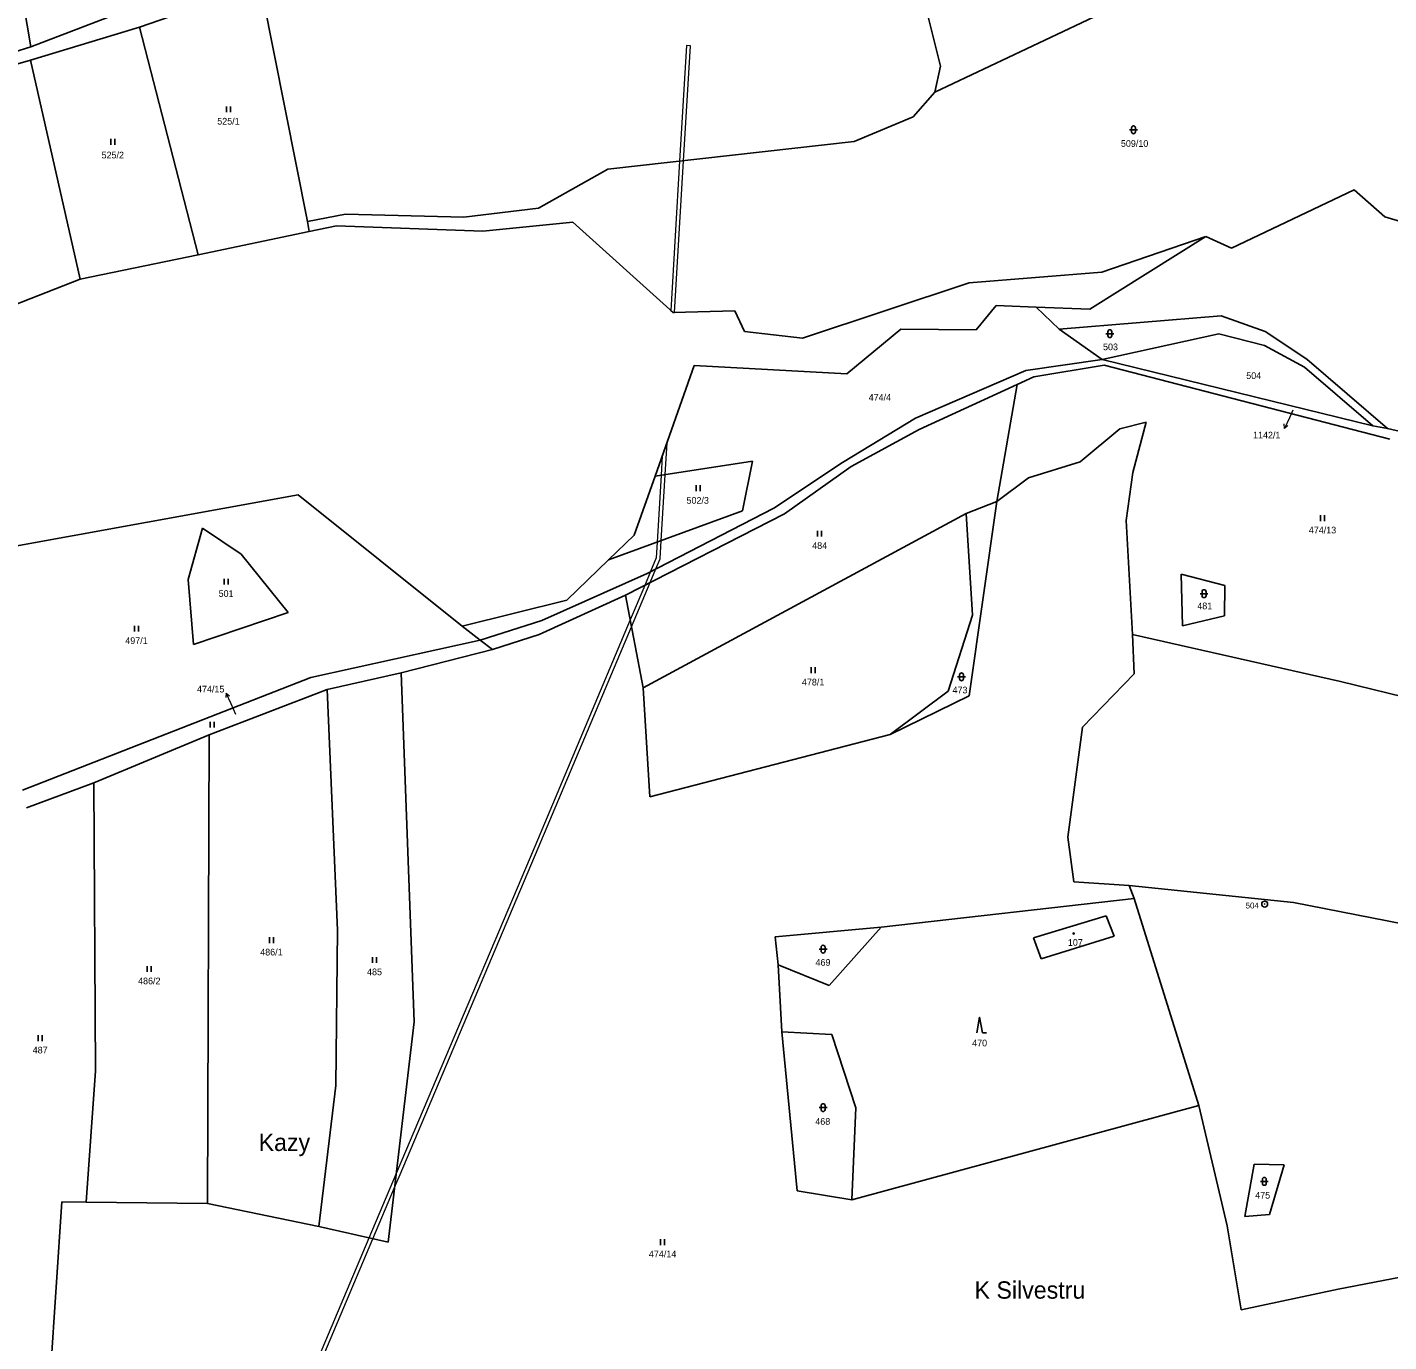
# Model space of a CAD drawing. Extents: x -765428 to -762163, y -1107632 to -1104975.
# Drawn here: x -764695.4 to -764349.6, y -1106368.4 to -1106034.3 of the extents above; entities that cross this region are included whole.
import ezdxf
from ezdxf.enums import TextEntityAlignment as Align

# ---------------------------------------------------------------- set-up
doc = ezdxf.new("R2010")
doc.units = 0
doc.header["$LTSCALE"] = 0.68
for name, color, linetype, lineweight in [('1', 7, 'Continuous', 25), ('13', 7, 'Continuous', 13), ('3', 7, 'Continuous', 25), ('5', 7, 'Continuous', 25), ('7', 7, 'Continuous', 13), ('8', 7, 'Continuous', 25)]:
    doc.layers.add(name, color=color, linetype=linetype, lineweight=lineweight)
doc.layers.add('2', color=7, linetype='Continuous')

msp = doc.modelspace()

# ---------------------------------------------------------------- linework, layer by layer
at = {"layer": '1'}
for p, q in [((-764479.66, -1105978.64), (-764463.45, -1106044.21)), ((-764659.81, -1106025.95), (-764694.55, -1106039.31)), ((-764636.2, -1106023.64), (-764666.9, -1106034.32)), ((-764624.21, -1106083.66), (-764636.2, -1106023.64)), ((-764411.29, -1106025.42), (-764464.92, -1106050.85)), ((-764666.9, -1106034.32), (-764694.57, -1106042.64)), ((-764666.9, -1106034.32), (-764652.02, -1106092.11)), ((-764694.55, -1106039.31), (-764729.59, -1106050.22)), ((-764694.57, -1106042.64), (-764729.45, -1106052.83)), ((-764681.98, -1106098.33), (-764694.57, -1106042.64)), ((-764463.45, -1106044.21), (-764464.92, -1106050.85)), ((-764464.92, -1106050.85), (-764470.36, -1106057.08)), ((-764470.36, -1106057.08), (-764485.37, -1106063.35)), ((-764485.37, -1106063.35), (-764547.95, -1106070.38)), ((-764547.95, -1106070.38), (-764565.59, -1106080.25)), ((-764358.34, -1106075.59), (-764389.51, -1106090.49)), ((-764350.58, -1106082.49), (-764358.34, -1106075.59)), ((-764614.6, -1106081.83), (-764624.21, -1106083.66)), ((-764584.5, -1106082.56), (-764614.6, -1106081.83)), ((-764565.59, -1106080.25), (-764584.5, -1106082.56)), ((-764624.21, -1106083.66), (-764623.79, -1106086.24)), ((-764623.79, -1106086.24), (-764616.88, -1106084.8)), ((-764616.88, -1106084.8), (-764579.71, -1106086.14)), ((-764579.71, -1106086.14), (-764556.8, -1106083.81)), ((-764556.8, -1106083.81), (-764531.32, -1106106.82)), ((-764332.67, -1106087.84), (-764350.58, -1106082.49)), ((-764652.02, -1106092.11), (-764623.79, -1106086.24)), ((-764396.06, -1106087.47), (-764425.53, -1106106)), ((-764422.48, -1106096.59), (-764396.06, -1106087.47)), ((-764396.06, -1106087.47), (-764389.51, -1106090.49)), ((-764681.98, -1106098.33), (-764652.02, -1106092.11)), ((-764718.88, -1106112.84), (-764681.98, -1106098.33)), ((-764456.18, -1106099.28), (-764422.48, -1106096.59)), ((-764498.48, -1106113.34), (-764456.18, -1106099.28)), ((-764449.31, -1106105.07), (-764454.37, -1106111.19)), ((-764439.17, -1106105.47), (-764449.31, -1106105.07)), ((-764425.53, -1106106), (-764439.17, -1106105.47)), ((-764433.28, -1106111.06), (-764439.17, -1106105.47)), ((-764531.32, -1106106.82), (-764515.69, -1106106.39)), ((-764515.69, -1106106.39), (-764513.19, -1106111.61)), ((-764433.28, -1106111.06), (-764392.12, -1106107.67)), ((-764392.12, -1106107.67), (-764380.95, -1106111.67)), ((-764513.19, -1106111.61), (-764498.48, -1106113.34)), ((-764473.5, -1106111.06), (-764487.22, -1106122.36)), ((-764454.37, -1106111.19), (-764473.5, -1106111.06)), ((-764433.28, -1106111.06), (-764422.39, -1106118.73)), ((-764422.39, -1106118.73), (-764392.72, -1106112.26)), ((-764392.72, -1106112.26), (-764381.17, -1106115.18)), ((-764380.95, -1106111.67), (-764370.39, -1106118.67)), ((-764381.17, -1106115.18), (-764370.95, -1106120.72)), ((-764422.39, -1106118.73), (-764441.8, -1106121.53)), ((-764353.63, -1106135.63), (-764422.39, -1106118.73)), ((-764370.39, -1106118.67), (-764349.87, -1106136.31)), ((-764535.95, -1106148.42), (-764525.98, -1106120.24)), ((-764487.22, -1106122.36), (-764525.98, -1106120.24)), ((-764441.8, -1106121.53), (-764469.76, -1106133.68)), ((-764439.74, -1106123.2), (-764443.95, -1106125.13)), ((-764421.87, -1106120.22), (-764439.74, -1106123.2)), ((-764349.26, -1106138.97), (-764421.87, -1106120.22)), ((-764370.95, -1106120.72), (-764353.63, -1106135.63)), ((-764443.95, -1106125.13), (-764468.83, -1106136.58)), ((-764449.12, -1106154.87), (-764443.95, -1106125.13)), ((-764469.76, -1106133.68), (-764488.31, -1106144.9)), ((-764468.83, -1106136.58), (-764486.09, -1106145.98)), ((-764417.89, -1106136.38), (-764427.98, -1106144.79)), ((-764411.16, -1106134.68), (-764417.89, -1106136.38)), ((-764414.59, -1106147.49), (-764411.16, -1106134.68)), ((-764349.87, -1106136.31), (-764353.63, -1106135.63)), ((-764322.27, -1106142.59), (-764349.87, -1106136.31)), ((-764511.22, -1106144.61), (-764535.95, -1106148.42)), ((-764511.22, -1106144.61), (-764513.71, -1106157.24)), ((-764488.31, -1106144.9), (-764505.79, -1106156.56)), ((-764486.09, -1106145.98), (-764503.06, -1106157.95)), ((-764427.98, -1106144.79), (-764441.05, -1106148.82)), ((-764416.27, -1106159.67), (-764414.59, -1106147.49)), ((-764541.27, -1106163.43), (-764535.95, -1106148.42)), ((-764441.05, -1106148.82), (-764449.12, -1106154.87)), ((-764626.62, -1106153.16), (-764703.88, -1106167.16)), ((-764584.97, -1106186.56), (-764626.62, -1106153.16)), ((-764513.71, -1106157.24), (-764547.74, -1106169.67)), ((-764503.06, -1106157.95), (-764543.46, -1106178.68)), ((-764538.95, -1106202.23), (-764456.9, -1106157.88)), ((-764505.79, -1106156.56), (-764537.98, -1106173.12)), ((-764449.12, -1106154.87), (-764456.9, -1106157.88)), ((-764456.9, -1106157.88), (-764455.3, -1106183.73)), ((-764449.12, -1106154.87), (-764456.18, -1106204.24)), ((-764414.64, -1106188.67), (-764416.27, -1106159.67)), ((-764654.57, -1106174.7), (-764650.91, -1106161.58)), ((-764650.91, -1106161.58), (-764641.08, -1106168.27)), ((-764541.27, -1106163.43), (-764547.74, -1106169.67)), ((-764629.16, -1106183.09), (-764641.08, -1106168.27)), ((-764547.74, -1106169.67), (-764558.39, -1106179.96)), ((-764654.57, -1106174.7), (-764653.24, -1106191.16)), ((-764537.98, -1106173.12), (-764564.72, -1106185.08)), ((-764402.31, -1106173.32), (-764401.95, -1106186.44)), ((-764391.25, -1106176.18), (-764402.31, -1106173.32)), ((-764543.46, -1106178.68), (-764565.42, -1106188.68)), ((-764538.95, -1106202.23), (-764543.46, -1106178.68)), ((-764391.28, -1106183.92), (-764391.25, -1106176.18)), ((-764558.39, -1106179.96), (-764584.97, -1106186.56)), ((-764653.24, -1106191.16), (-764629.16, -1106183.09)), ((-764564.72, -1106185.08), (-764580.36, -1106190.07)), ((-764455.3, -1106183.73), (-764461.45, -1106203.04)), ((-764401.95, -1106186.44), (-764391.28, -1106183.92)), ((-764580.36, -1106190.07), (-764584.97, -1106186.56)), ((-764565.42, -1106188.68), (-764577.21, -1106192.49)), ((-764414.64, -1106188.67), (-764414.22, -1106198.62)), ((-764361.8, -1106200.63), (-764414.64, -1106188.67)), ((-764580.36, -1106190.07), (-764623.38, -1106199.56)), ((-764600.46, -1106198.36), (-764577.21, -1106192.49)), ((-764577.21, -1106192.49), (-764580.36, -1106190.07)), ((-764600.46, -1106198.36), (-764619.26, -1106202.61)), ((-764597.13, -1106287.13), (-764600.46, -1106198.36)), ((-764414.22, -1106198.62), (-764427.37, -1106212.24)), ((-764623.38, -1106199.56), (-764696.66, -1106228.18)), ((-764649.26, -1106214.16), (-764619.26, -1106202.61)), ((-764616.58, -1106263.81), (-764619.26, -1106202.61)), ((-764537.28, -1106229.92), (-764538.95, -1106202.23)), ((-764324.05, -1106209.8), (-764361.8, -1106200.63)), ((-764461.45, -1106203.04), (-764476.2, -1106214.05)), ((-764456.18, -1106204.24), (-764476.2, -1106214.05)), ((-764427.37, -1106212.24), (-764431.09, -1106240.18)), ((-764678.54, -1106226.38), (-764649.26, -1106214.16)), ((-764649.62, -1106333.24), (-764649.26, -1106214.16)), ((-764476.2, -1106214.05), (-764537.28, -1106229.92)), ((-764678.54, -1106226.38), (-764695.59, -1106232.66)), ((-764678.06, -1106299.53), (-764678.54, -1106226.38)), ((-764431.09, -1106240.18), (-764429.54, -1106251.48)), ((-764429.54, -1106251.48), (-764415.51, -1106252.4)), ((-764415.51, -1106252.4), (-764373.79, -1106256.8)), ((-764414.24, -1106255.78), (-764415.51, -1106252.4)), ((-764478.5, -1106263.01), (-764414.24, -1106255.78)), ((-764414.24, -1106255.78), (-764397.8, -1106308.36)), ((-764373.79, -1106256.8), (-764311.37, -1106269.03)), ((-764421.36, -1106260.16), (-764439.8, -1106265.76)), ((-764421.36, -1106260.16), (-764419.36, -1106265.3)), ((-764617.07, -1106303.26), (-764616.58, -1106263.81)), ((-764505.48, -1106265.49), (-764478.5, -1106263.01)), ((-764478.5, -1106263.01), (-764491.69, -1106277.89)), ((-764505.48, -1106265.49), (-764504.68, -1106272.6)), ((-764437.86, -1106271.12), (-764439.8, -1106265.76)), ((-764419.36, -1106265.3), (-764437.86, -1106271.12)), ((-764503.76, -1106289.67), (-764504.68, -1106272.6)), ((-764491.69, -1106277.89), (-764504.68, -1106272.6)), ((-764603.77, -1106343.13), (-764597.13, -1106287.13)), ((-764503.76, -1106289.67), (-764499.82, -1106330.05)), ((-764491.03, -1106290.32), (-764503.76, -1106289.67)), ((-764484.94, -1106308.96), (-764491.03, -1106290.32)), ((-764680.46, -1106332.91), (-764678.06, -1106299.53)), ((-764617.07, -1106303.26), (-764621.39, -1106339.15)), ((-764485.95, -1106332.32), (-764397.8, -1106308.36)), ((-764485.95, -1106332.32), (-764484.94, -1106308.96)), ((-764397.8, -1106308.36), (-764390.63, -1106338.98)), ((-764383.79, -1106323.26), (-764386.09, -1106336.57)), ((-764376.16, -1106323.42), (-764383.79, -1106323.26)), ((-764379.86, -1106336.06), (-764376.16, -1106323.42)), ((-764499.82, -1106330.05), (-764485.95, -1106332.32)), ((-764690.66, -1106394.2), (-764686.67, -1106332.83)), ((-764686.67, -1106332.83), (-764680.46, -1106332.91)), ((-764680.46, -1106332.91), (-764649.62, -1106333.24)), ((-764649.62, -1106333.24), (-764621.39, -1106339.15)), ((-764386.09, -1106336.57), (-764379.86, -1106336.06)), ((-764621.39, -1106339.15), (-764603.77, -1106343.13)), ((-764390.63, -1106338.98), (-764387.02, -1106360.28)), ((-764362.45, -1106355.01), (-764310.86, -1106345.11)), ((-764387.02, -1106360.28), (-764362.45, -1106355.01))]:
    msp.add_line(p, q, dxfattribs=at)
msp.add_lwpolyline([(-764713.46, -1105926.07), (-764700.09, -1106006.14), (-764694.55, -1106039.31)], dxfattribs=at)
at = {"layer": '13'}
for points in [[(-764530.97, -1106106.81), (-764528.69, -1106068.22), (-764526.97, -1106039.03), (-764527.97, -1106038.97), (-764529.7, -1106068.33), (-764531.94, -1106106.26), (-764531.32, -1106106.82)], [(-764534.41, -1106148.18), (-764533.39, -1106148.03), (-764532.91, -1106139.83), (-764534.11, -1106143.23)], [(-764535.41, -1106165.16), (-764534.38, -1106164.79), (-764533.39, -1106148.03), (-764534.41, -1106148.18)], [(-764537.1, -1106172.67), (-764535.72, -1106171.96), (-764534.66, -1106169.44), (-764534.38, -1106164.79), (-764535.41, -1106165.16), (-764535.64, -1106169.2)], [(-764538.58, -1106176.18), (-764537.2, -1106175.47), (-764535.72, -1106171.96), (-764537.1, -1106172.67)], [(-764542.26, -1106184.92), (-764541.93, -1106186.69), (-764537.2, -1106175.47), (-764538.58, -1106176.18)], [(-764653.41, -1106450.97), (-764640.59, -1106420.4), (-764634.82, -1106406.65), (-764607.62, -1106342.26), (-764602.12, -1106329.23), (-764600.71, -1106325.88), (-764565.61, -1106242.92), (-764541.93, -1106186.69), (-764542.26, -1106184.92), (-764566.53, -1106242.54), (-764601.7, -1106325.65), (-764608.62, -1106342.04), (-764635.74, -1106406.27), (-764641.65, -1106420.36), (-764654.47, -1106450.91)]]:
    msp.add_lwpolyline(points, close=True, dxfattribs=at)
at = {"layer": '3'}
for p, q in [((-764644.791, -1106055.92), (-764644.791, -1106054.42)), ((-764643.79, -1106055.92), (-764643.79, -1106054.42)), ((-764415.411, -1106060.361), (-764413.409, -1106060.361)), ((-764414.911, -1106059.861), (-764414.911, -1106060.862)), ((-764413.909, -1106060.862), (-764413.909, -1106059.861)), ((-764674.181, -1106064.16), (-764674.181, -1106062.66)), ((-764673.18, -1106064.16), (-764673.18, -1106062.66)), ((-764421.421, -1106112.191), (-764419.419, -1106112.191)), ((-764420.921, -1106111.691), (-764420.921, -1106112.692)), ((-764419.919, -1106112.692), (-764419.919, -1106111.691)), ((-764525.481, -1106152.23), (-764525.481, -1106150.73)), ((-764524.48, -1106152.23), (-764524.48, -1106150.73)), ((-764366.911, -1106159.83), (-764366.911, -1106158.33)), ((-764365.91, -1106159.83), (-764365.91, -1106158.33)), ((-764494.651, -1106163.78), (-764494.651, -1106162.28)), ((-764493.65, -1106163.78), (-764493.65, -1106162.28)), ((-764645.431, -1106175.97), (-764645.431, -1106174.47)), ((-764644.43, -1106175.97), (-764644.43, -1106174.47)), ((-764397.491, -1106178.271), (-764395.489, -1106178.271)), ((-764396.991, -1106177.771), (-764396.991, -1106178.772)), ((-764395.989, -1106178.772), (-764395.989, -1106177.771)), ((-764668.191, -1106187.92), (-764668.191, -1106186.42)), ((-764667.19, -1106187.92), (-764667.19, -1106186.42)), ((-764496.311, -1106198.47), (-764496.311, -1106196.97)), ((-764495.31, -1106198.47), (-764495.31, -1106196.97)), ((-764459.101, -1106199.411), (-764457.099, -1106199.411)), ((-764458.601, -1106198.911), (-764458.601, -1106199.912)), ((-764457.599, -1106199.912), (-764457.599, -1106198.911)), ((-764648.991, -1106212.31), (-764648.991, -1106210.81)), ((-764647.99, -1106212.31), (-764647.99, -1106210.81)), ((-764633.911, -1106267.09), (-764633.911, -1106265.59)), ((-764632.91, -1106267.09), (-764632.91, -1106265.59)), ((-764494.271, -1106268.631), (-764492.269, -1106268.631)), ((-764493.771, -1106268.131), (-764493.771, -1106269.132)), ((-764492.769, -1106269.132), (-764492.769, -1106268.131)), ((-764607.731, -1106272.12), (-764607.731, -1106270.62)), ((-764606.73, -1106272.12), (-764606.73, -1106270.62)), ((-764664.941, -1106274.42), (-764664.941, -1106272.92)), ((-764663.94, -1106274.42), (-764663.94, -1106272.92)), ((-764692.661, -1106292), (-764692.661, -1106290.5)), ((-764691.66, -1106292), (-764691.66, -1106290.5)), ((-764452.74, -1106289.92), (-764451.744, -1106289.92)), ((-764494.261, -1106308.891), (-764492.259, -1106308.891)), ((-764493.761, -1106308.391), (-764493.761, -1106309.392)), ((-764492.759, -1106309.392), (-764492.759, -1106308.391)), ((-764381.671, -1106327.141), (-764381.671, -1106328.142)), ((-764380.669, -1106328.142), (-764380.669, -1106327.141)), ((-764382.171, -1106327.641), (-764380.169, -1106327.641)), ((-764534.541, -1106343.83), (-764534.541, -1106342.33)), ((-764533.54, -1106343.83), (-764533.54, -1106342.33))]:
    msp.add_line(p, q, dxfattribs=at)
msp.add_lwpolyline([(-764452.74, -1106289.92), (-764453.49, -1106285.92), (-764454.24, -1106289.92)], dxfattribs=at)
for centre, start, end in [((-764414.41, -1106059.8609), 0, 180), ((-764414.41, -1106060.8609), 180, 359.98789), ((-764420.42, -1106111.6909), 0, 180), ((-764420.42, -1106112.6909), 180, 359.98789), ((-764396.49, -1106177.7709), 0, 180), ((-764396.49, -1106178.7709), 180, 359.98789), ((-764458.1, -1106198.9109), 0, 180), ((-764458.1, -1106199.9109), 180, 359.98789), ((-764493.27, -1106268.1309), 0, 180), ((-764493.27, -1106269.1309), 180, 359.98789), ((-764493.26, -1106308.3909), 0, 180), ((-764493.26, -1106309.3909), 180, 359.98789), ((-764381.17, -1106327.1409), 0, 180), ((-764381.17, -1106328.1409), 180, 359.98789)]:
    msp.add_arc(centre, 0.5, start, end, dxfattribs=at)
at = {"layer": '5'}
msp.add_circle((-764429.5968, -1106264.6392), 0.175, dxfattribs=at)
at = {"layer": '7'}
for p, q in [((-764376.088, -1106136.26), (-764375.211, -1106135.564)), ((-764644.918, -1106203.54), (-764644.949, -1106204.659))]:
    msp.add_line(p, q, dxfattribs=at)
for points in [[(-764373.94, -1106131.65), (-764374.82, -1106133.54), (-764376.088, -1106136.26), (-764376.119, -1106135.141)], [(-764642.41, -1106208.97), (-764643.65, -1106206.26), (-764644.918, -1106203.54), (-764644.041, -1106204.236)]]:
    msp.add_lwpolyline(points, dxfattribs=at)
at = {"layer": '8'}
for radius in [0.75, 0.03]:
    msp.add_circle((-764381.08, -1106257.1598), radius, dxfattribs=at)

# ---------------------------------------------------------------- texts
at = {"layer": '2'}
for s, p in [('525/1', (-764644.32, -1106059.045)), ('525/2', (-764673.7, -1106067.645)), ('474/13', (-764366.4, -1106162.955)), ('484', (-764494.139, -1106166.905)), ('501', (-764644.919, -1106179.095)), ('497/1', (-764667.68, -1106191.045)), ('478/1', (-764495.8, -1106201.595)), ('486/1', (-764633.4, -1106270.215)), ('485', (-764607.219, -1106275.245)), ('486/2', (-764664.43, -1106277.545)), ('487', (-764692.149, -1106295.125)), ('474/14', (-764534.03, -1106346.955))]:
    msp.add_text(s, height=1.7, dxfattribs=at).set_placement(p, align=Align.CENTER)
for s, p in [('509/10', (-764417.61, -1106064.705)), ('503', (-764422.15, -1106116.395)), ('504', (-764385.77, -1106123.695)), ('474/4', (-764481.68, -1106129.225)), ('502/3', (-764527.96, -1106155.415)), ('481', (-764398.2, -1106182.235)), ('473', (-764460.38, -1106203.605)), ('107', (-764431.08, -1106267.775)), ('469', (-764495.19, -1106272.835)), ('470', (-764455.4, -1106293.325)), ('468', (-764495.24, -1106313.255)), ('475', (-764383.49, -1106332.015))]:
    msp.add_text(s, height=1.7, dxfattribs=at).set_placement(p)
for s, p in [('1142/1', (-764377.089, -1106138.825)), ('474/15', (-764645.349, -1106203.385))]:
    msp.add_text(s, height=1.7, dxfattribs=at).set_placement(p, align=Align.RIGHT)
at = {"layer": '7'}
for s, p in [('Kazy', (-764636.65, -1106319.92)), ('K Silvestru', (-764454.78, -1106357.45))]:
    msp.add_text(s, height=4.4, dxfattribs=at).set_placement(p)
at = {"layer": '8'}
msp.add_text('504', height=1.5, dxfattribs=at).set_placement((-764382.579, -1106258.277), align=Align.RIGHT)

doc.saveas('drawing.dxf')
